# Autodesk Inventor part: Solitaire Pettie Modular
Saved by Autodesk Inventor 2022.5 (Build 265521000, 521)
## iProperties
Created: 2025-01
Part Number: Solitaire Pettie Modular
Material: Generic
Document SubType Name: Modeling
Designer: AdminForWorker
Density: 1 g/cm^3
Appearance: Default
Title: Solitaire Pettie Modular
Author: AdminForWorker
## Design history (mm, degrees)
feature "Solitaire Pettie Modular"
body "Solid1"
